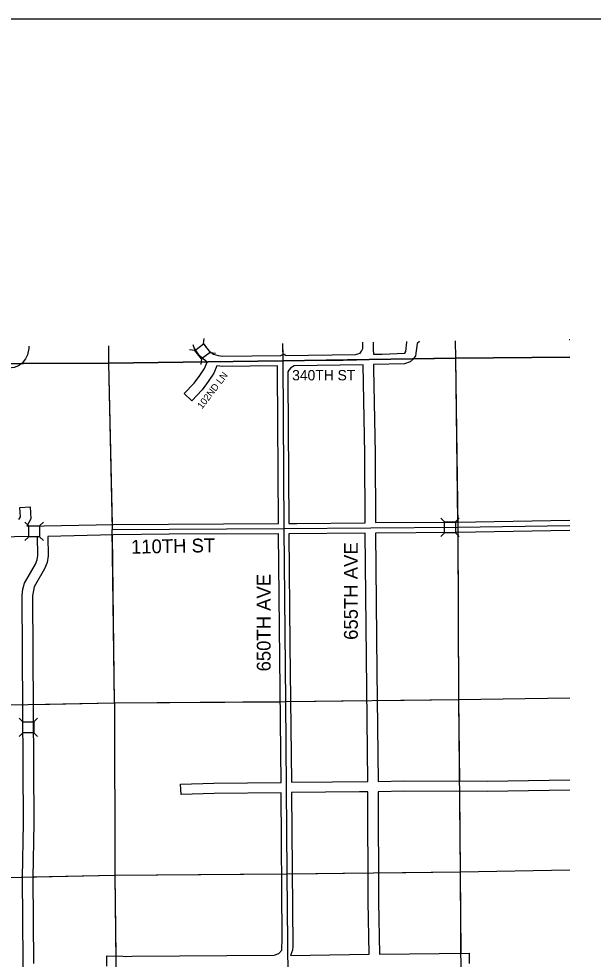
# Model space of a CAD drawing. Extents: x 10133 to 81668, y 5524 to 11018.
# Drawn here: x 15547 to 15963, y 9263 to 9944 of the extents above; entities that cross this region are included whole.
import ezdxf

# ---------------------------------------------------------------- set-up
doc = ezdxf.new("R2010")
doc.units = 0
doc.layers.add('Default', color=7, linetype='Continuous')
doc.layers.add('Level 3', color=7, linetype='Continuous')

msp = doc.modelspace()

# ---------------------------------------------------------------- linework, layer by layer
at = {"layer": 'Default'}
for p, q in [((15680.6, 9708.74), (15681.12, 9712.62)), ((15674.38, 9704), (15670.5, 9704.52)), ((15685.35, 9702.52), (15689.22, 9702)), ((15679.12, 9697.77), (15678.6, 9693.9)), ((15554.07, 9576.88), (15551.3, 9579.65)), ((15561.9, 9576.9), (15564.66, 9579.67)), ((15855.14, 9579.81), (15852.37, 9582.57)), ((15862.97, 9579.84), (15865.72, 9582.62)), ((15855.17, 9571.98), (15852.42, 9569.21)), ((15863, 9572.01), (15865.77, 9569.26)), ((15554.09, 9569.06), (15551.33, 9566.29)), ((15561.91, 9569.08), (15564.68, 9566.32)), ((15549.87, 9435.1), (15547.11, 9437.87)), ((15557.7, 9435.1), (15560.47, 9437.87)), ((15549.87, 9427.27), (15547.11, 9424.51)), ((15557.7, 9427.27), (15560.47, 9424.51))]:
    msp.add_line(p, q, dxfattribs=at)
for points in [[(15546.8, 9581.68), (15548.1, 9583.52), (15547.7, 9590.23), (15555.18, 9590.74), (15555.48, 9582), (15552.72, 9576.72), (15615.45, 9578.01), (15734.91, 9578.72), (15734.28, 9689.14), (15734.19, 9692.73), (15694.49, 9692.25), (15690.17, 9692.73), (15688.11, 9687.56), (15684.09, 9681.38), (15679.57, 9675.54), (15672.08, 9667.55), (15666.61, 9672.68), (15673.83, 9680.37), (15678.01, 9685.78), (15681.42, 9690.95), (15683.18, 9695.45), (15677.75, 9699.95), (15673.87, 9705.92), (15673.2, 9708.09)], [(15611.86, 9707.19), (15611.84, 9694.7)], [(15611.86, 9707.19), (15611.84, 9694.7)], [(15681.22, 9708.21), (15682.31, 9706.22), (15685.11, 9703.24), (15687.95, 9701.37), (15691.14, 9700.19), (15694.51, 9699.75)], [(15694.51, 9699.75), (15736.56, 9700.27), (15739.25, 9701.5), (15739.79, 9700.32), (15790.73, 9700.94), (15793.93, 9702.09), (15795.11, 9703.37), (15795.97, 9705.34), (15795.92, 9709.89)], [(15737.86, 9709.04), (15737.96, 9700.29)], [(15737.86, 9709.04), (15738, 9696.54)], [(15803.41, 9710), (15803.47, 9704.94), (15803.65, 9701.24), (15810.05, 9701.34)], [(15837, 9710.49), (15835.37, 9708.91), (15833.99, 9700.08), (15832.48, 9697.56), (15830.27, 9695.64), (15826.1, 9694.23), (15803.77, 9693.75), (15803.74, 9690.91), (15804.91, 9629.25), (15805.12, 9579.31), (15863.74, 9579.68)], [(15810.05, 9701.34), (15826.31, 9702.01), (15827.14, 9703.22), (15827.76, 9710.05), (15827.91, 9710.36)], [(15862.76, 9710.87), (15862.97, 9698.38)], [(15862.76, 9710.87), (15862.97, 9698.38)], [(15945.75, 9711.53), (15945.37, 9711.71)], [(15554.1, 9706.99), (15554.11, 9705.4), (15553.18, 9700.76), (15551.81, 9697.9), (15549.3, 9694.83), (15546.76, 9692.93), (15543.62, 9691.51), (15537.95, 9690.77), (15492.44, 9690.53), (15492.72, 9648.51), (15493.65, 9575.79)], [(15006.1, 9688.72), (15112.48, 9689.85), (15238.47, 9691.82), (15363.32, 9692.72), (15488.7, 9694.26), (15611.84, 9694.7), (15738, 9696.54), (15862.97, 9698.38), (15945.75, 9699.07)], [(15945.75, 9699.07), (15862.97, 9698.38), (15738, 9696.54), (15611.84, 9694.7), (15488.7, 9694.26), (15363.32, 9692.72), (15238.47, 9691.82), (15112.48, 9689.85), (15006.1, 9688.72)], [(15488.7, 9694.26), (15611.84, 9694.7)], [(15548.82, 9694.47), (15611.84, 9694.7), (15682.78, 9695.73)], [(15548.82, 9694.47), (15611.84, 9694.7)], [(15611.84, 9694.7), (15738, 9696.54)], [(15611.84, 9694.7), (15682.78, 9695.73)], [(15611.84, 9694.7), (15614.49, 9577.99)], [(15611.84, 9694.7), (15614.58, 9574.25)], [(15737.41, 9696.53), (15745.35, 9696.66)], [(15737.41, 9696.53), (15737.41, 9696.53)], [(15738, 9696.54), (15862.97, 9698.38)], [(15738, 9696.54), (15738.69, 9574.98)], [(15748.14, 9578.75), (15797.63, 9579.17), (15797.41, 9629.14), (15796.27, 9693.65), (15746.24, 9692.93), (15743.72, 9691.4), (15742.34, 9689.69), (15741.77, 9688.36), (15741.73, 9683.27), (15742.4, 9578.74), (15748.14, 9578.75)], [(15745.35, 9696.66), (15750.18, 9696.74), (15757.83, 9696.81), (15775.78, 9697.04), (15781.7, 9697.01), (15790.16, 9697.21), (15790.77, 9697.18)], [(15790.77, 9697.18), (15790.88, 9697.17), (15791.39, 9697.18), (15795.66, 9697.4), (15798.6, 9697.42), (15800, 9697.44)], [(15832.74, 9697.93), (15862.97, 9698.38), (15945.75, 9699.07)], [(15832.74, 9697.93), (15862.97, 9698.38)], [(15862.97, 9698.38), (15945.75, 9699.07)], [(15862.97, 9698.38), (15945.75, 9699.07)], [(15862.97, 9698.38), (15864.59, 9579.7)], [(15862.97, 9698.38), (15864.64, 9575.95)], [(15863.74, 9579.68), (15945.75, 9581.01)], [(15610.56, 9258.16), (15610.63, 9265.66), (15622.18, 9265.53), (15623.99, 9265.14), (15628.93, 9265.56), (15731.86, 9266.14), (15735.03, 9267.32), (15737.28, 9269.93), (15737.66, 9278.42), (15736.8, 9383.64), (15688.23, 9383.22), (15664.33, 9382.53), (15663.85, 9390.01), (15688.11, 9390.72), (15736.74, 9391.14), (15734.97, 9571.22), (15655.66, 9570.88), (15615.55, 9570.51), (15567.98, 9569.26), (15568.23, 9555.29), (15567.41, 9550.5), (15565.5, 9545.76), (15557.95, 9532.76), (15556.7, 9526.27), (15557.86, 9361.83), (15557.06, 9322.26), (15557.46, 9260.1)], [(15614.58, 9574.25), (15738.69, 9574.98)], [(15616.14, 9448.83), (15614.58, 9574.25)], [(15738.69, 9574.98), (15864.64, 9575.95)], [(15738.69, 9574.98), (15739.95, 9449.73)], [(15774.08, 9391.61), (15799.5, 9391.99), (15797.71, 9571.68), (15742.47, 9571.24), (15743.2, 9491.11), (15744.24, 9391.35), (15774.08, 9391.61)], [(15945.75, 9573.6), (15863.88, 9572.18), (15805.21, 9571.81), (15805.99, 9471.49), (15807, 9391.96), (15826.08, 9392.35)], [(15864.64, 9575.95), (15945.75, 9577.25)], [(15864.64, 9575.95), (15865.33, 9451.3)], [(15864.66, 9572.2), (15865.33, 9451.3)], [(15550.57, 9201.82), (15549.56, 9322.22), (15550.36, 9361.81), (15549.2, 9526.54), (15549.74, 9531.14), (15550.97, 9535.5), (15558.87, 9549.26), (15560.18, 9552.48), (15560.73, 9555.54), (15560.48, 9569.24), (15493.71, 9568.29), (15493.77, 9512.21), (15494.38, 9484.78), (15495.18, 9370.99), (15496.59, 9369.5), (15494.69, 9367.71), (15494.12, 9365.19), (15492.17, 9365.63), (15480.77, 9360.07), (15475.79, 9358.45), (15463.39, 9357.79), (15433.12, 9358.16), (15433.12, 9289.05), (15434.07, 9253.7)], [(15616.14, 9448.83), (15614.63, 9570.5)], [(15490.79, 9446.54), (15616.14, 9448.83)], [(15557.43, 9447.75), (15616.14, 9448.83)], [(15616.14, 9448.83), (15739.95, 9449.73)], [(15616.14, 9448.83), (15736.15, 9449.7)], [(15616.14, 9448.83), (15616.48, 9324.14)], [(15616.14, 9448.83), (15616.48, 9324.14)], [(15739.95, 9449.73), (15865.33, 9451.3)], [(15739.95, 9449.73), (15741.02, 9325.07)], [(15743.7, 9449.78), (15798.87, 9450.47)], [(15806.37, 9450.56), (15865.33, 9451.3)], [(15865.33, 9451.3), (15945.75, 9452.46)], [(15865.33, 9451.3), (15945.75, 9452.46)], [(15865.33, 9451.3), (15865.9, 9392.05)], [(15865.33, 9451.3), (15866.53, 9326.62)], [(15494.56, 9446.61), (15549.93, 9447.62)], [(15826.08, 9392.35), (15886.01, 9392.2), (15945.75, 9393.08)], [(15743.71, 9266.07), (15800.6, 9266.84), (15799.93, 9304.95), (15799.52, 9384.49), (15793.61, 9384.52), (15744.3, 9383.85), (15745.19, 9272.71), (15745.03, 9269.8), (15743.71, 9266.07)], [(15945.75, 9385.58), (15886.1, 9384.7), (15826.08, 9384.85), (15807.02, 9384.46), (15807.43, 9305.01), (15808.1, 9266.9), (15872.86, 9267.73), (15872.94, 9260.24)], [(15865.97, 9384.55), (15866.53, 9326.62)], [(15741.02, 9325.07), (15866.53, 9326.62)], [(15807.33, 9325.89), (15866.53, 9326.62)], [(15866.53, 9326.62), (15945.75, 9327.94)], [(15866.53, 9326.62), (15945.75, 9327.94)], [(15866.53, 9326.62), (15866.87, 9267.69)], [(15866.53, 9326.62), (15867.25, 9201.79)], [(15491.64, 9321.53), (15616.48, 9324.14)], [(15491.64, 9321.53), (15549.58, 9322.74)], [(15557.08, 9322.9), (15616.48, 9324.14)], [(15616.48, 9324.14), (15741.02, 9325.07)], [(15616.48, 9324.14), (15737.29, 9325.04)], [(15616.48, 9324.14), (15617.16, 9265.59)], [(15616.48, 9324.14), (15617.93, 9199.35)], [(15741.02, 9325.07), (15742.15, 9200.28)], [(15744.78, 9325.12), (15799.83, 9325.8)]]:
    msp.add_lwpolyline(points, dxfattribs=at)
for points in [[(15680.6, 9708.74), (15685.35, 9702.52), (15679.12, 9697.77), (15674.38, 9704)], [(15855.14, 9579.81), (15862.97, 9579.84), (15863, 9572.01), (15855.17, 9571.98)], [(15554.07, 9576.88), (15561.9, 9576.9), (15561.91, 9569.08), (15554.09, 9569.06)], [(15549.87, 9427.27), (15549.87, 9435.1), (15557.7, 9435.1), (15557.7, 9427.27)]]:
    msp.add_lwpolyline(points, close=True, dxfattribs=at)
at = {"layer": 'Level 3'}
msp.add_lwpolyline([(13732.52, 9944.02), (16867.53, 9944.02), (16867.53, 7924.02), (13732.52, 7924.02)], close=True, dxfattribs=at)

# ---------------------------------------------------------------- texts
at = {"layer": 'Default'}
for s, height, rotation, p in [('102ND LN', 5, 52.40156, (15679.52, 9661.2)), ('110TH ST', 10, 1.13673, (15628.2, 9556.78)), ('655TH AVE', 10, 90, (15792.32, 9494.46)), ('650TH AVE', 10, 90, (15729.19, 9471.6))]:
    msp.add_text(s, height=height, rotation=rotation, dxfattribs=at).set_placement(p)
msp.add_text('340TH ST', height=7.5, dxfattribs=at).set_placement((15744.8, 9682.3))

doc.saveas('drawing.dxf')
